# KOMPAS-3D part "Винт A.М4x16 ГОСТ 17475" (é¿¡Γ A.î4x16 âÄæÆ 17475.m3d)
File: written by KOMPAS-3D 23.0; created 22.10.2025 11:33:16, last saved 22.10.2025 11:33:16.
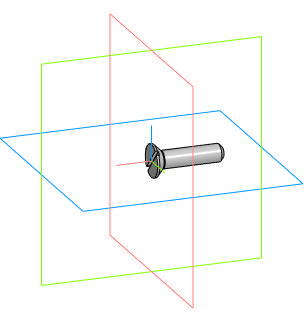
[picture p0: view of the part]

Document properties: Автор: ARM_513_VVK; Полное имя файла: F:\Демо\Демо вариант космос\Винт A.М4x16 ГОСТ 17475.m3d

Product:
- Part/product: Винт A.М4x16 ГОСТ 17475

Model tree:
1. Операция без истории:1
